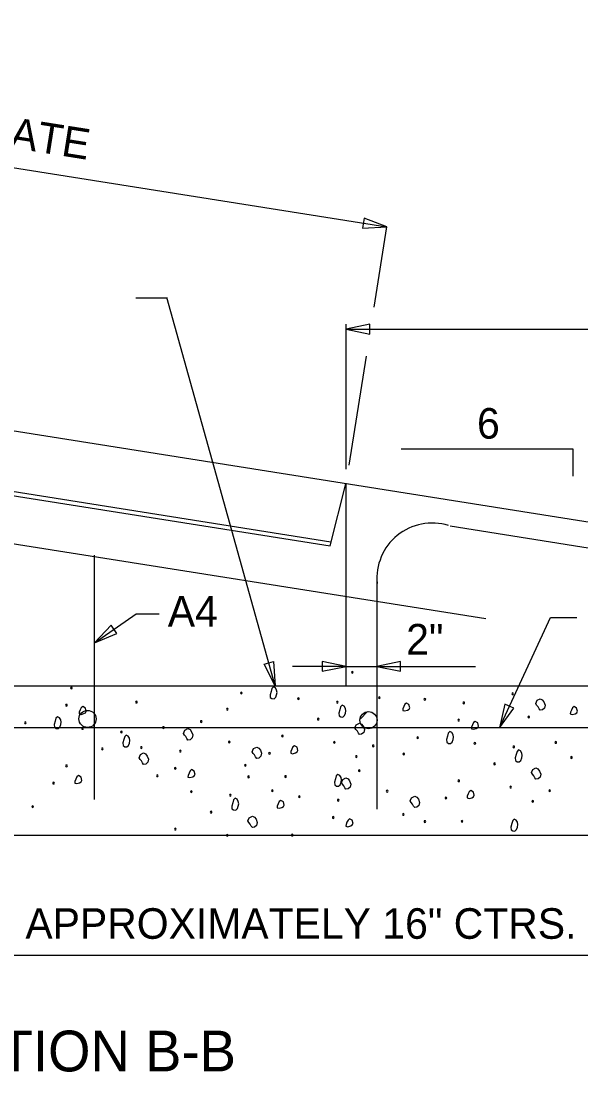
# Model space of a CAD drawing. Extents: x -439.1 to -407.9, y -458.1 to -436.2.
# Drawn here: x -432.28 to -429.53, y -450.33 to -445.18 of the extents above; entities that cross this region are included whole.
import ezdxf

# ---------------------------------------------------------------- set-up
doc = ezdxf.new("R2010")
doc.units = 0
doc.layers.add('Level 4', color=7, linetype='Continuous')
doc.layers.add('Level 45', color=7, linetype='Continuous')

msp = doc.modelspace()

# ---------------------------------------------------------------- linework, layer by layer
at = {"layer": 'Level 4'}
for p, q in [((-435.643, -445.37), (-430.4863, -446.1867)), ((-438.971, -446.1333), (-425.1939, -448.3149)), ((-430.5486, -446.5804), (-430.4863, -446.1867)), ((-431.7165, -446.5341), (-431.5643, -446.5341)), ((-431.0331, -448.437), (-431.5644, -446.5338)), ((-430.6863, -447.3755), (-430.6863, -446.6645)), ((-430.6863, -446.6886), (-425.1938, -446.6886)), ((-430.6712, -447.3547), (-430.5866, -446.8205)), ((-435.9228, -446.9132), (-430.76, -447.7311)), ((-435.9281, -446.9342), (-430.7645, -447.7516)), ((-436.074, -447.1452), (-430.0008, -448.107)), ((-430.4166, -447.2754), (-429.5745, -447.2754)), ((-429.5745, -447.2754), (-429.5745, -447.4088)), ((-430.7645, -447.7516), (-430.6865, -447.4476)), ((-430.6865, -447.4455), (-430.6865, -448.4367)), ((-430.1751, -447.6534), (-425.5068, -448.3937)), ((-431.9202, -447.7973), (-431.9202, -448.9943)), ((-430.5353, -447.9138), (-430.5353, -449.0426)), ((-431.9198, -448.2265), (-431.7151, -448.084)), ((-431.7151, -448.084), (-431.6026, -448.084)), ((-429.9338, -448.6427), (-429.6844, -448.1018)), ((-429.6844, -448.1018), (-429.5542, -448.1018)), ((-430.6863, -448.3421), (-430.9488, -448.3421)), ((-430.6863, -448.3421), (-430.535, -448.3421)), ((-430.535, -448.3421), (-430.2725, -448.3421)), ((-430.535, -448.3421), (-430.0511, -448.3421)), ((-435.9228, -448.4367), (-425.1939, -448.4367)), ((-430.6158, -448.5996), (-430.5802, -448.564)), ((-436.4384, -448.6425), (-430.5353, -448.6425)), ((-430.5353, -448.6425), (-425.3798, -448.6425)), ((-436.7019, -449.1696), (-425.1939, -449.1696)), ((-425.1938, -449.759), (-436.7024, -449.759))]:
    msp.add_line(p, q, dxfattribs=at)
for points in [[(-430.6048, -446.1924), (-430.4863, -446.1867), (-430.5972, -446.1447)], [(-430.5701, -446.6645), (-430.6863, -446.6886), (-430.5701, -446.7128)], [(-431.8382, -448.1404), (-431.9198, -448.2265), (-431.8106, -448.18)], [(-431.0411, -448.3186), (-431.0331, -448.437), (-431.0876, -448.3316)], [(-430.8024, -448.3662), (-430.6863, -448.3421), (-430.8024, -448.3179)], [(-430.4188, -448.3179), (-430.535, -448.3421), (-430.4188, -448.3662)], [(-431.0419, -448.4425), (-431.0499, -448.45), (-431.0536, -448.4646), (-431.0589, -448.4814), (-431.0575, -448.4945), (-431.0493, -448.5001), (-431.0393, -448.501), (-431.0309, -448.4936), (-431.0264, -448.4815), (-431.0245, -448.4697), (-431.0264, -448.4581), (-431.0324, -448.4473), (-431.0419, -448.4425)], [(-430.3903, -448.5219), (-430.3981, -448.5278), (-430.4033, -448.5387), (-430.408, -448.55), (-430.4085, -448.5582), (-430.399, -448.5605), (-430.3851, -448.5569), (-430.3773, -448.5522), (-430.3734, -448.5452), (-430.3777, -448.5293), (-430.3903, -448.5219)], [(-429.9071, -448.5271), (-429.9338, -448.6427), (-429.8633, -448.5473)], [(-429.7564, -448.5241), (-429.7499, -448.5084), (-429.7344, -448.5008), (-429.7241, -448.5056), (-429.7162, -448.5163), (-429.7105, -448.5316), (-429.7136, -448.5462), (-429.7237, -448.555), (-429.7344, -448.5566), (-429.7398, -448.5495), (-429.7448, -448.5397), (-429.7518, -448.5321), (-429.7564, -448.5241)], [(-431.9766, -448.5387), (-431.9844, -448.5446), (-431.9896, -448.5556), (-431.9943, -448.5668), (-431.9948, -448.5751), (-431.9853, -448.5774), (-431.9714, -448.5738), (-431.9636, -448.569), (-431.9597, -448.5621), (-431.964, -448.5461), (-431.9766, -448.5387)], [(-430.7049, -448.5325), (-430.7128, -448.54), (-430.7166, -448.5546), (-430.7219, -448.5714), (-430.7205, -448.5845), (-430.7123, -448.5901), (-430.7023, -448.591), (-430.6939, -448.5836), (-430.6893, -448.5715), (-430.6875, -448.5598), (-430.6893, -448.5481), (-430.6953, -448.5373), (-430.7049, -448.5325)], [(-429.5685, -448.5391), (-429.5763, -448.545), (-429.5815, -448.556), (-429.5862, -448.5672), (-429.5867, -448.5754), (-429.5772, -448.5778), (-429.5633, -448.5741), (-429.5555, -448.5694), (-429.5516, -448.5624), (-429.5559, -448.5465), (-429.5685, -448.5391)], [(-432.1004, -448.5888), (-432.1083, -448.5963), (-432.1121, -448.6109), (-432.1174, -448.6277), (-432.116, -448.6408), (-432.1078, -448.6464), (-432.0978, -448.6472), (-432.0894, -448.6399), (-432.0848, -448.6278), (-432.083, -448.616), (-432.0848, -448.6044), (-432.0908, -448.5936), (-432.1004, -448.5888)], [(-430.6424, -448.6436), (-430.6358, -448.6279), (-430.6203, -448.6203), (-430.61, -448.6251), (-430.6021, -448.6358), (-430.5964, -448.6511), (-430.5995, -448.6657), (-430.6096, -448.6745), (-430.6203, -448.6761), (-430.6257, -448.669), (-430.6307, -448.6592), (-430.6377, -448.6516), (-430.6424, -448.6436)], [(-430.0533, -448.6119), (-430.0611, -448.6178), (-430.0662, -448.6287), (-430.071, -448.64), (-430.0714, -448.6482), (-430.062, -448.6506), (-430.0481, -448.6469), (-430.0403, -448.6422), (-430.0364, -448.6352), (-430.0406, -448.6193), (-430.0533, -448.6119)], [(-431.7634, -448.6788), (-431.7713, -448.6863), (-431.7751, -448.7009), (-431.7804, -448.7177), (-431.7789, -448.7308), (-431.7707, -448.7364), (-431.7608, -448.7372), (-431.7523, -448.7299), (-431.7478, -448.7178), (-431.746, -448.706), (-431.7478, -448.6944), (-431.7538, -448.6836), (-431.7634, -448.6788)], [(-431.4833, -448.6708), (-431.4767, -448.655), (-431.4612, -448.6474), (-431.4509, -448.6522), (-431.443, -448.663), (-431.4373, -448.6782), (-431.4404, -448.6928), (-431.4505, -448.7017), (-431.4612, -448.7032), (-431.4667, -448.6962), (-431.4716, -448.6863), (-431.4786, -448.6788), (-431.4833, -448.6708)], [(-430.1771, -448.662), (-430.185, -448.6694), (-430.1888, -448.684), (-430.1941, -448.7008), (-430.1927, -448.7139), (-430.1845, -448.7195), (-430.1745, -448.7204), (-430.1661, -448.713), (-430.1615, -448.7009), (-430.1597, -448.6892), (-430.1615, -448.6776), (-430.1675, -448.6667), (-430.1771, -448.662)], [(-430.9392, -448.7314), (-430.947, -448.7373), (-430.9522, -448.7483), (-430.9569, -448.7595), (-430.9573, -448.7677), (-430.9479, -448.7701), (-430.934, -448.7664), (-430.9262, -448.7617), (-430.9223, -448.7548), (-430.9265, -448.7388), (-430.9392, -448.7314)], [(-431.7008, -448.7899), (-431.6943, -448.7742), (-431.6788, -448.7666), (-431.6685, -448.7714), (-431.6606, -448.7821), (-431.6549, -448.7974), (-431.658, -448.812), (-431.668, -448.8208), (-431.6788, -448.8224), (-431.6842, -448.8153), (-431.6891, -448.8055), (-431.6962, -448.7979), (-431.7008, -448.7899)], [(-431.1462, -448.7608), (-431.1397, -448.745), (-431.1242, -448.7374), (-431.1139, -448.7423), (-431.106, -448.753), (-431.1003, -448.7682), (-431.1034, -448.7828), (-431.1134, -448.7917), (-431.1242, -448.7932), (-431.1296, -448.7862), (-431.1345, -448.7763), (-431.1416, -448.7688), (-431.1462, -448.7608)], [(-429.8401, -448.752), (-429.848, -448.7594), (-429.8517, -448.774), (-429.857, -448.7908), (-429.8556, -448.8039), (-429.8474, -448.8095), (-429.8375, -448.8104), (-429.829, -448.803), (-429.8245, -448.7909), (-429.8226, -448.7792), (-429.8245, -448.7676), (-429.8305, -448.7567), (-429.8401, -448.752)], [(-429.7775, -448.8631), (-429.7709, -448.8473), (-429.7554, -448.8397), (-429.7451, -448.8446), (-429.7373, -448.8553), (-429.7316, -448.8705), (-429.7347, -448.8851), (-429.7447, -448.894), (-429.7554, -448.8955), (-429.7609, -448.8885), (-429.7658, -448.8786), (-429.7728, -448.8711), (-429.7775, -448.8631)], [(-431.9976, -448.8777), (-432.0054, -448.8836), (-432.0106, -448.8946), (-432.0154, -448.9058), (-432.0158, -448.914), (-432.0063, -448.9164), (-431.9925, -448.9127), (-431.9847, -448.908), (-431.9808, -448.901), (-431.985, -448.8851), (-431.9976, -448.8777)], [(-431.443, -448.8485), (-431.4508, -448.8544), (-431.456, -448.8654), (-431.4608, -448.8766), (-431.4612, -448.8849), (-431.4517, -448.8872), (-431.4379, -448.8836), (-431.4301, -448.8788), (-431.4262, -448.8719), (-431.4304, -448.8559), (-431.443, -448.8485)], [(-430.726, -448.8715), (-430.7339, -448.8789), (-430.7376, -448.8936), (-430.7429, -448.9103), (-430.7415, -448.9234), (-430.7333, -448.929), (-430.7234, -448.9299), (-430.7149, -448.9225), (-430.7104, -448.9104), (-430.7086, -448.8987), (-430.7104, -448.8871), (-430.7164, -448.8763), (-430.726, -448.8715)], [(-430.7088, -448.9117), (-430.7022, -448.896), (-430.6867, -448.8883), (-430.6764, -448.8932), (-430.6685, -448.9039), (-430.6628, -448.9192), (-430.6659, -448.9338), (-430.676, -448.9426), (-430.6867, -448.9442), (-430.6922, -448.9371), (-430.6971, -448.9273), (-430.7041, -448.9197), (-430.7088, -448.9117)], [(-431.2298, -448.9886), (-431.2378, -448.9961), (-431.2415, -449.0107), (-431.2468, -449.0275), (-431.2454, -449.0406), (-431.2372, -449.0462), (-431.2272, -449.047), (-431.2188, -449.0397), (-431.2143, -449.0276), (-431.2124, -449.0158), (-431.2143, -449.0042), (-431.2203, -448.9934), (-431.2298, -448.9886)], [(-430.3717, -449.0017), (-430.3652, -448.986), (-430.3497, -448.9784), (-430.3394, -448.9832), (-430.3315, -448.9939), (-430.3258, -449.0092), (-430.3289, -449.0238), (-430.3389, -449.0326), (-430.3497, -449.0342), (-430.3551, -449.0271), (-430.3601, -449.0173), (-430.3671, -449.0097), (-430.3717, -449.0017)], [(-430.0743, -448.9508), (-430.0821, -448.9567), (-430.0873, -448.9677), (-430.0921, -448.9789), (-430.0925, -448.9872), (-430.083, -448.9895), (-430.0691, -448.9859), (-430.0614, -448.9811), (-430.0575, -448.9742), (-430.0617, -448.9583), (-430.0743, -448.9508)], [(-431.0056, -448.9995), (-431.0134, -449.0054), (-431.0186, -449.0163), (-431.0233, -449.0276), (-431.0238, -449.0358), (-431.0143, -449.0381), (-431.0004, -449.0345), (-430.9926, -449.0298), (-430.9887, -449.0228), (-430.993, -449.0069), (-431.0056, -448.9995)], [(-431.1673, -449.0997), (-431.1607, -449.084), (-431.1452, -449.0764), (-431.1349, -449.0812), (-431.127, -449.0919), (-431.1213, -449.1072), (-431.1245, -449.1218), (-431.1345, -449.1306), (-431.1452, -449.1322), (-431.1507, -449.1251), (-431.1556, -449.1153), (-431.1626, -449.1077), (-431.1673, -449.0997)], [(-430.6686, -449.0895), (-430.6763, -449.0954), (-430.6815, -449.1063), (-430.6863, -449.1176), (-430.6867, -449.1258), (-430.6772, -449.1282), (-430.6634, -449.1245), (-430.6556, -449.1198), (-430.6517, -449.1128), (-430.6559, -449.0969), (-430.6686, -449.0895)], [(-429.8611, -449.0909), (-429.869, -449.0984), (-429.8728, -449.113), (-429.8781, -449.1298), (-429.8767, -449.1429), (-429.8685, -449.1485), (-429.8585, -449.1494), (-429.8501, -449.142), (-429.8455, -449.1299), (-429.8437, -449.1182), (-429.8455, -449.1065), (-429.8516, -449.0957), (-429.8611, -449.0909)]]:
    msp.add_lwpolyline(points, close=True, dxfattribs=at)
for centre in [(-431.9534, -448.5996), (-430.576, -448.6057)]:
    msp.add_circle(centre, 0.042, dxfattribs=at)
for centre, radius, start, end in [((-430.2638, -447.9103), 0.2712, 72.9091, 185.2347), ((-430.6551, -448.371), 0.00416, 0, 180), ((-430.6551, -448.371), 0.00416, 180, 0), ((-432.0324, -448.4478), 0.00416, 0, 180), ((-432.0324, -448.4478), 0.00416, 180, 0), ((-431.1997, -448.4724), 0.00416, 0, 180), ((-431.1997, -448.4724), 0.00416, 180, 0), ((-429.8692, -448.4764), 0.00416, 0, 180), ((-429.8692, -448.4764), 0.00416, 180, 0), ((-432.057, -448.5323), 0.00416, 0, 180), ((-431.7136, -448.5173), 0.00416, 0, 180), ((-431.7136, -448.5173), 0.00416, 180, 0), ((-430.9196, -448.5), 0.00416, 0, 180), ((-430.9196, -448.5), 0.00416, 180, 0), ((-430.7288, -448.5176), 0.00416, 0, 180), ((-430.7288, -448.5176), 0.00416, 180, 0), ((-430.5228, -448.4957), 0.00416, 0, 180), ((-430.5228, -448.4957), 0.00416, 180, 0), ((-430.2998, -448.5034), 0.00416, 0, 180), ((-430.2998, -448.5034), 0.00416, 180, 0), ((-430.1091, -448.5209), 0.00416, 0, 180), ((-430.1091, -448.5209), 0.00416, 180, 0), ((-432.057, -448.5323), 0.00416, 180, 0), ((-431.2678, -448.5521), 0.00416, 0, 180), ((-431.2678, -448.5521), 0.00416, 180, 0), ((-432.2581, -448.6187), 0.00416, 0, 180), ((-432.2581, -448.6187), 0.00416, 180, 0), ((-431.3961, -448.6126), 0.00416, 0, 180), ((-431.3961, -448.6126), 0.00416, 180, 0), ((-430.8227, -448.6005), 0.00416, 0, 180), ((-430.8227, -448.6005), 0.00416, 180, 0), ((-430.1337, -448.6055), 0.00416, 0, 180), ((-430.1337, -448.6055), 0.00416, 180, 0), ((-429.7903, -448.5905), 0.00416, 0, 180), ((-429.7903, -448.5905), 0.00416, 180, 0), ((-431.978, -448.6463), 0.00416, 0, 180), ((-431.978, -448.6463), 0.00416, 180, 0), ((-431.7873, -448.6639), 0.00416, 0, 180), ((-431.7873, -448.6639), 0.00416, 180, 0), ((-431.5813, -448.642), 0.00416, 0, 180), ((-431.5813, -448.642), 0.00416, 180, 0), ((-430.9981, -448.6837), 0.00416, 0, 180), ((-430.9981, -448.6837), 0.00416, 180, 0), ((-431.6896, -448.74), 0.00416, 0, 180), ((-431.259, -448.7131), 0.00416, 0, 180), ((-431.259, -448.7131), 0.00416, 180, 0), ((-430.7438, -448.7145), 0.00416, 0, 180), ((-430.7438, -448.7145), 0.00416, 180, 0), ((-430.553, -448.7321), 0.00416, 0, 180), ((-430.553, -448.7321), 0.00416, 180, 0), ((-430.3348, -448.6919), 0.00416, 0, 180), ((-430.3348, -448.6919), 0.00416, 180, 0), ((-430.0547, -448.7195), 0.00416, 0, 180), ((-430.0547, -448.7195), 0.00416, 180, 0), ((-429.8639, -448.737), 0.00416, 0, 180), ((-429.8639, -448.737), 0.00416, 180, 0), ((-429.6579, -448.7151), 0.00416, 0, 180), ((-429.6579, -448.7151), 0.00416, 180, 0), ((-431.8812, -448.7468), 0.00416, 0, 180), ((-431.8812, -448.7468), 0.00416, 180, 0), ((-431.6896, -448.74), 0.00416, 180, 0), ((-431.4988, -448.7576), 0.00416, 0, 180), ((-431.4988, -448.7576), 0.00416, 180, 0), ((-431.0614, -448.7682), 0.00416, 0, 180), ((-431.0614, -448.7682), 0.00416, 180, 0), ((-430.6357, -448.7843), 0.00416, 0, 180), ((-430.6357, -448.7843), 0.00416, 180, 0), ((-430.403, -448.7715), 0.00416, 0, 180), ((-430.403, -448.7715), 0.00416, 180, 0), ((-429.5812, -448.7888), 0.00416, 0, 180), ((-432.0566, -448.83), 0.00416, 0, 180), ((-432.0566, -448.83), 0.00416, 180, 0), ((-431.5234, -448.8421), 0.00416, 0, 180), ((-431.18, -448.8271), 0.00416, 0, 180), ((-431.18, -448.8271), 0.00416, 180, 0), ((-429.9579, -448.8199), 0.00416, 0, 180), ((-429.9579, -448.8199), 0.00416, 180, 0), ((-429.5812, -448.7888), 0.00416, 180, 0), ((-431.6115, -448.8783), 0.00416, 0, 180), ((-431.6115, -448.8783), 0.00416, 180, 0), ((-431.5234, -448.8421), 0.00416, 180, 0), ((-431.1642, -448.8836), 0.00416, 0, 180), ((-431.1642, -448.8836), 0.00416, 180, 0), ((-430.9825, -448.8822), 0.00416, 0, 180), ((-430.9825, -448.8822), 0.00416, 180, 0), ((-430.6216, -448.8536), 0.00416, 0, 180), ((-430.6216, -448.8536), 0.00416, 180, 0), ((-432.1199, -448.9145), 0.00416, 0, 180), ((-432.1199, -448.9145), 0.00416, 180, 0), ((-430.1333, -448.9031), 0.00416, 0, 180), ((-430.1333, -448.9031), 0.00416, 180, 0), ((-429.879, -448.934), 0.00416, 0, 180), ((-429.879, -448.934), 0.00416, 180, 0), ((-431.4445, -448.9561), 0.00416, 0, 180), ((-431.4445, -448.9561), 0.00416, 180, 0), ((-431.2537, -448.9737), 0.00416, 0, 180), ((-431.2537, -448.9737), 0.00416, 180, 0), ((-431.0477, -448.9518), 0.00416, 0, 180), ((-431.0477, -448.9518), 0.00416, 180, 0), ((-430.9151, -448.981), 0.00416, 0, 180), ((-430.9151, -448.981), 0.00416, 180, 0), ((-430.7244, -448.9985), 0.00416, 0, 180), ((-430.4845, -448.954), 0.00416, 0, 180), ((-430.4845, -448.954), 0.00416, 180, 0), ((-430.1966, -448.9876), 0.00416, 0, 180), ((-430.1966, -448.9876), 0.00416, 180, 0), ((-429.6882, -448.9515), 0.00416, 0, 180), ((-429.6882, -448.9515), 0.00416, 180, 0), ((-432.2227, -449.0299), 0.00416, 0, 180), ((-432.2227, -449.0299), 0.00416, 180, 0), ((-430.7244, -448.9985), 0.00416, 180, 0), ((-429.7708, -449.0038), 0.00416, 0, 180), ((-429.7708, -449.0038), 0.00416, 180, 0), ((-431.3477, -449.0566), 0.00416, 0, 180), ((-431.3477, -449.0566), 0.00416, 180, 0), ((-430.749, -449.0831), 0.00416, 0, 180), ((-430.749, -449.0831), 0.00416, 180, 0), ((-430.4055, -449.0681), 0.00416, 0, 180), ((-430.4055, -449.0681), 0.00416, 180, 0), ((-430.1176, -449.1017), 0.00416, 0, 180), ((-431.523, -449.1398), 0.00416, 0, 180), ((-431.523, -449.1398), 0.00416, 180, 0), ((-430.2994, -449.1031), 0.00416, 0, 180), ((-430.2994, -449.1031), 0.00416, 180, 0), ((-430.1176, -449.1017), 0.00416, 180, 0), ((-431.2687, -449.1706), 0.00416, 0, 180), ((-431.2687, -449.1706), 0.00416, 180, 0), ((-430.9501, -449.1695), 0.00416, 0, 180), ((-430.9501, -449.1695), 0.00416, 180, 0)]:
    msp.add_arc(centre, radius, start, end, dxfattribs=at)

# ---------------------------------------------------------------- texts
for s, height, p in [('6', 0.15, (-430.044, -447.2252)), ('A4', 0.15, (-431.5601, -448.147)), ('SECTION B-B', 0.2, (-432.9346, -450.3282))]:
    msp.add_text(s, height=height, dxfattribs=at).set_placement(p)
at = {"layer": 'Level 45'}
msp.add_text("5' X 2' GRATE AND BEARING PLATE", height=0.15, rotation=351, dxfattribs=at).set_placement((-435.3332, -445.3228))
for s, p in [('2"', (-430.3912, -448.2839)), ('C BARS AT APPROXIMATELY 16" CTRS.', (-433.3729, -449.6779))]:
    msp.add_text(s, height=0.15, dxfattribs=at).set_placement(p)

doc.saveas('drawing.dxf')
